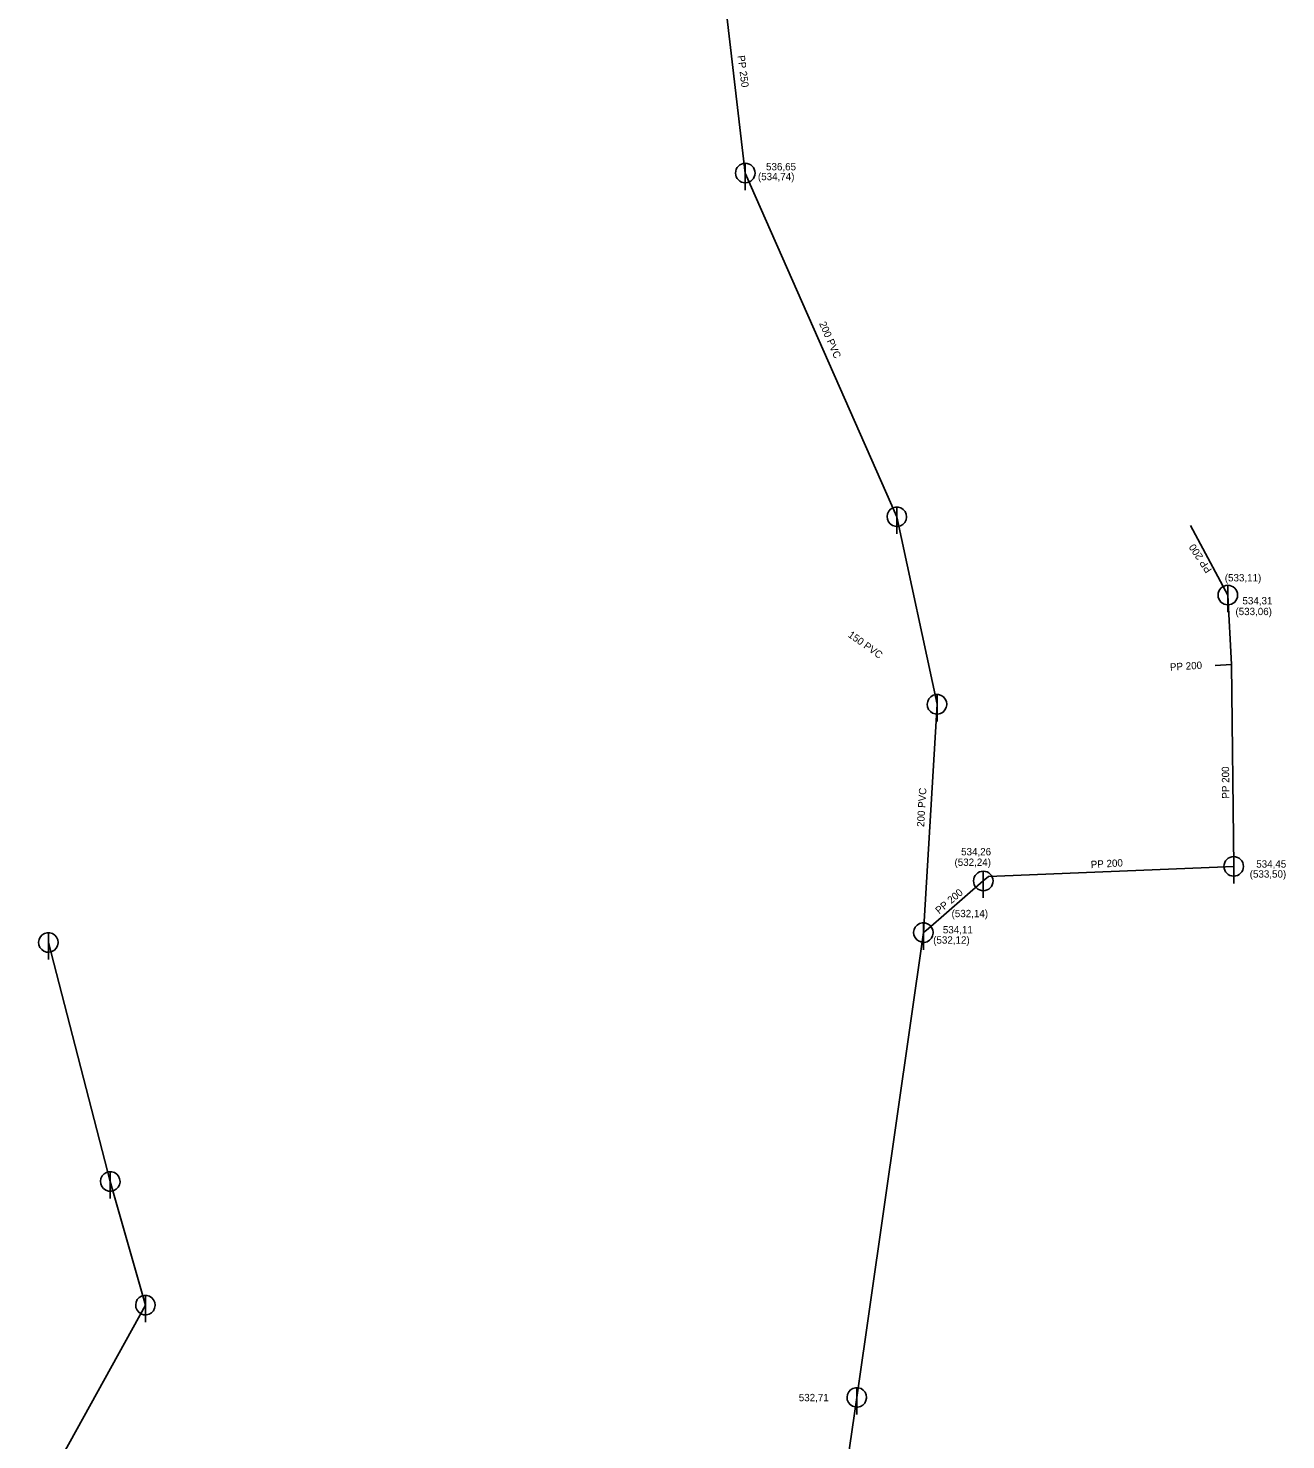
# Model space of a CAD drawing. Extents: x -476058 to -471893, y -1155786 to -1152000.
# Drawn here: x -473239.4 to -473110.6, y -1153747.8 to -1153603.3 of the extents above; entities that cross this region are included whole.
import ezdxf

# ---------------------------------------------------------------- set-up
doc = ezdxf.new("R2010")
doc.units = 0
for name, color, linetype in [('Vrstva 10', 7, 'Continuous'), ('Vrstva 17', 7, 'Continuous'), ('Vrstva 18', 7, 'Continuous'), ('Vrstva 19', 7, 'Continuous'), ('Vrstva 3', 7, 'Continuous'), ('Vrstva 4', 7, 'Continuous'), ('Vrstva 40', 7, 'Continuous'), ('Vrstva 45', 7, 'Continuous'), ('Vrstva 46', 7, 'Continuous'), ('Vrstva 50', 7, 'Continuous')]:
    doc.layers.add(name, color=color, linetype=linetype)

msp = doc.modelspace()

# ---------------------------------------------------------------- linework, layer by layer
at = {"layer": 'Vrstva 10'}
for p, q in [((-473165.97, -1153617.09), (-473165.97, -1153619.84)), ((-473150.45, -1153652.27), (-473150.45, -1153655.02)), ((-473116.57, -1153660.29), (-473116.57, -1153663.04)), ((-473146.34, -1153671.47), (-473146.34, -1153674.22)), ((-473115.97, -1153688.06), (-473115.97, -1153690.81)), ((-473141.6, -1153689.55), (-473141.6, -1153692.29)), ((-473147.73, -1153694.84), (-473147.73, -1153697.59)), ((-473237.31, -1153695.85), (-473237.31, -1153698.6)), ((-473230.97, -1153720.31), (-473230.97, -1153723.06)), ((-473227.37, -1153732.96), (-473227.37, -1153735.71)), ((-473154.55, -1153742.42), (-473154.55, -1153745.17))]:
    msp.add_line(p, q, dxfattribs=at)
for points in [[(-473149.45, -1153653.27), (-473149.49, -1153652.99), (-473149.61, -1153652.73), (-473149.79, -1153652.52), (-473150.03, -1153652.36), (-473150.3, -1153652.28), (-473150.58, -1153652.28), (-473150.85, -1153652.35), (-473151.09, -1153652.5), (-473151.28, -1153652.71), (-473151.4, -1153652.96), (-473151.45, -1153653.24), (-473151.42, -1153653.52), (-473151.31, -1153653.78), (-473151.13, -1153654), (-473150.9, -1153654.16), (-473150.63, -1153654.25), (-473150.35, -1153654.26), (-473150.08, -1153654.2), (-473149.83, -1153654.05), (-473149.64, -1153653.85), (-473149.51, -1153653.6), (-473149.45, -1153653.32), (-473149.45, -1153653.27)], [(-473145.34, -1153672.47), (-473145.38, -1153672.19), (-473145.5, -1153671.94), (-473145.68, -1153671.72), (-473145.92, -1153671.57), (-473146.18, -1153671.48), (-473146.47, -1153671.48), (-473146.74, -1153671.55), (-473146.98, -1153671.7), (-473147.17, -1153671.91), (-473147.29, -1153672.17), (-473147.34, -1153672.44), (-473147.31, -1153672.73), (-473147.2, -1153672.99), (-473147.02, -1153673.2), (-473146.79, -1153673.37), (-473146.52, -1153673.46), (-473146.24, -1153673.47), (-473145.97, -1153673.4), (-473145.72, -1153673.26), (-473145.53, -1153673.05), (-473145.4, -1153672.8), (-473145.34, -1153672.53), (-473145.34, -1153672.47)], [(-473146.73, -1153695.84), (-473146.77, -1153695.56), (-473146.89, -1153695.3), (-473147.07, -1153695.09), (-473147.3, -1153694.94), (-473147.58, -1153694.85), (-473147.86, -1153694.85), (-473148.13, -1153694.92), (-473148.37, -1153695.07), (-473148.56, -1153695.28), (-473148.68, -1153695.53), (-473148.73, -1153695.81), (-473148.7, -1153696.09), (-473148.59, -1153696.35), (-473148.41, -1153696.57), (-473148.18, -1153696.73), (-473147.91, -1153696.82), (-473147.63, -1153696.84), (-473147.36, -1153696.77), (-473147.11, -1153696.63), (-473146.92, -1153696.42), (-473146.79, -1153696.17), (-473146.73, -1153695.9), (-473146.73, -1153695.84)], [(-473236.31, -1153696.85), (-473236.35, -1153696.57), (-473236.47, -1153696.31), (-473236.65, -1153696.1), (-473236.89, -1153695.94), (-473237.16, -1153695.86), (-473237.44, -1153695.86), (-473237.71, -1153695.93), (-473237.95, -1153696.08), (-473238.14, -1153696.29), (-473238.26, -1153696.54), (-473238.31, -1153696.82), (-473238.28, -1153697.1), (-473238.17, -1153697.36), (-473237.99, -1153697.58), (-473237.76, -1153697.74), (-473237.49, -1153697.83), (-473237.21, -1153697.84), (-473236.94, -1153697.78), (-473236.69, -1153697.64), (-473236.5, -1153697.43), (-473236.37, -1153697.18), (-473236.31, -1153696.9), (-473236.31, -1153696.85)], [(-473229.97, -1153721.31), (-473230.01, -1153721.03), (-473230.13, -1153720.78), (-473230.31, -1153720.56), (-473230.55, -1153720.41), (-473230.82, -1153720.33), (-473231.1, -1153720.32), (-473231.37, -1153720.4), (-473231.61, -1153720.54), (-473231.8, -1153720.75), (-473231.92, -1153721.01), (-473231.97, -1153721.29), (-473231.94, -1153721.57), (-473231.83, -1153721.83), (-473231.65, -1153722.05), (-473231.42, -1153722.21), (-473231.16, -1153722.3), (-473230.87, -1153722.31), (-473230.6, -1153722.24), (-473230.35, -1153722.1), (-473230.16, -1153721.9), (-473230.03, -1153721.65), (-473229.97, -1153721.37), (-473229.97, -1153721.31)], [(-473226.37, -1153733.96), (-473226.41, -1153733.69), (-473226.53, -1153733.43), (-473226.71, -1153733.21), (-473226.95, -1153733.06), (-473227.22, -1153732.98), (-473227.5, -1153732.97), (-473227.77, -1153733.05), (-473228.01, -1153733.2), (-473228.2, -1153733.4), (-473228.33, -1153733.66), (-473228.37, -1153733.94), (-473228.34, -1153734.22), (-473228.23, -1153734.48), (-473228.05, -1153734.7), (-473227.82, -1153734.86), (-473227.56, -1153734.95), (-473227.27, -1153734.96), (-473227, -1153734.89), (-473226.76, -1153734.75), (-473226.56, -1153734.55), (-473226.43, -1153734.3), (-473226.38, -1153734.02), (-473226.37, -1153733.96)], [(-473153.55, -1153743.42), (-473153.59, -1153743.14), (-473153.71, -1153742.88), (-473153.89, -1153742.67), (-473154.12, -1153742.52), (-473154.4, -1153742.43), (-473154.68, -1153742.43), (-473154.95, -1153742.5), (-473155.19, -1153742.65), (-473155.38, -1153742.86), (-473155.5, -1153743.11), (-473155.55, -1153743.39), (-473155.52, -1153743.67), (-473155.41, -1153743.93), (-473155.23, -1153744.15), (-473155, -1153744.31), (-473154.73, -1153744.4), (-473154.45, -1153744.42), (-473154.18, -1153744.35), (-473153.93, -1153744.21), (-473153.74, -1153744), (-473153.61, -1153743.75), (-473153.55, -1153743.48), (-473153.55, -1153743.42)]]:
    msp.add_lwpolyline(points, dxfattribs=at)
for centre in [(-473165.97, -1153618.09), (-473116.57, -1153661.29), (-473115.97, -1153689.06), (-473141.6, -1153690.55)]:
    msp.add_circle(centre, 1, dxfattribs=at)
at = {"layer": 'Vrstva 40'}
msp.add_lwpolyline([(-473168.32, -1153597.89), (-473165.97, -1153618.09)], dxfattribs=at)
at = {"layer": 'Vrstva 45'}
for points in [[(-473147.73, -1153695.84), (-473154.55, -1153743.42)], [(-473154.55, -1153743.42), (-473161.62, -1153791.92)]]:
    msp.add_lwpolyline(points, dxfattribs=at)
at = {"layer": 'Vrstva 46'}
for points in [[(-473165.97, -1153618.09), (-473150.45, -1153653.27)], [(-473150.45, -1153653.27), (-473146.34, -1153672.47)], [(-473146.34, -1153672.47), (-473147.73, -1153695.84)]]:
    msp.add_lwpolyline(points, dxfattribs=at)
at = {"layer": 'Vrstva 50'}
for p, q in [((-473115.97, -1153689.06), (-473141.06, -1153690.11)), ((-473141.06, -1153690.11), (-473141.6, -1153690.55))]:
    msp.add_line(p, q, dxfattribs=at)
for points in [[(-473120.39, -1153654.16), (-473116.57, -1153661.29), (-473116.18, -1153668.38)], [(-473117.86, -1153668.49), (-473116.18, -1153668.38)], [(-473116.18, -1153668.38), (-473115.97, -1153689.06)], [(-473141.6, -1153690.55), (-473147.26, -1153695.44), (-473147.73, -1153695.84)], [(-473237.31, -1153696.85), (-473230.97, -1153721.31)], [(-473230.97, -1153721.31), (-473227.37, -1153733.96)], [(-473227.37, -1153733.96), (-473239.37, -1153755.71)]]:
    msp.add_lwpolyline(points, dxfattribs=at)

# ---------------------------------------------------------------- texts
at = {"layer": 'Vrstva 17'}
msp.add_text('PP 250', height=0.75, rotation=277.3077, dxfattribs=at).set_placement((-473166.76, -1153606.09))
at = {"layer": 'Vrstva 18'}
for rotation, p in [(293.7994, (-473158.43, -1153633.48)), (86.5959, (-473147.66, -1153685.04))]:
    msp.add_text('200 PVC', height=0.75, rotation=rotation, dxfattribs=at).set_placement(p)
at = {"layer": 'Vrstva 19'}
for s, rotation, p in [('PP 200', 123.6598, (-473118.16, -1153658.71)), ('150 PVC', 324.5832, (-473155.52, -1153665.51)), ('PP 200', 3.5126, (-473122.47, -1153669.03)), ('PP 200', 90.5929, (-473116.41, -1153682.12)), ('PP 200', 3.3151, (-473130.58, -1153689.25)), ('PP 200', 40.3648, (-473146.12, -1153693.98))]:
    msp.add_text(s, height=0.75, rotation=rotation, dxfattribs=at).set_placement(p)
at = {"layer": 'Vrstva 3'}
for s, p in [('536,65', (-473163.84, -1153617.81)), ('534,31', (-473115.07, -1153662.24)), ('534,26', (-473143.87, -1153687.93)), ('534,45', (-473113.66, -1153689.19)), ('534,11', (-473145.74, -1153695.92)), ('532,71', (-473160.49, -1153743.81))]:
    msp.add_text(s, height=0.75, dxfattribs=at).set_placement(p)
at = {"layer": 'Vrstva 4'}
for s, p in [('(534,74)', (-473164.67, -1153618.82)), ('(533,11)', (-473116.88, -1153659.89)), ('(533,06)', (-473115.79, -1153663.34)), ('(532,24)', (-473144.55, -1153689.01)), ('(533,50)', (-473114.33, -1153690.21)), ('(532,14)', (-473144.85, -1153694.26)), ('(532,12)', (-473146.73, -1153696.97))]:
    msp.add_text(s, height=0.75, dxfattribs=at).set_placement(p)

doc.saveas('drawing.dxf')
